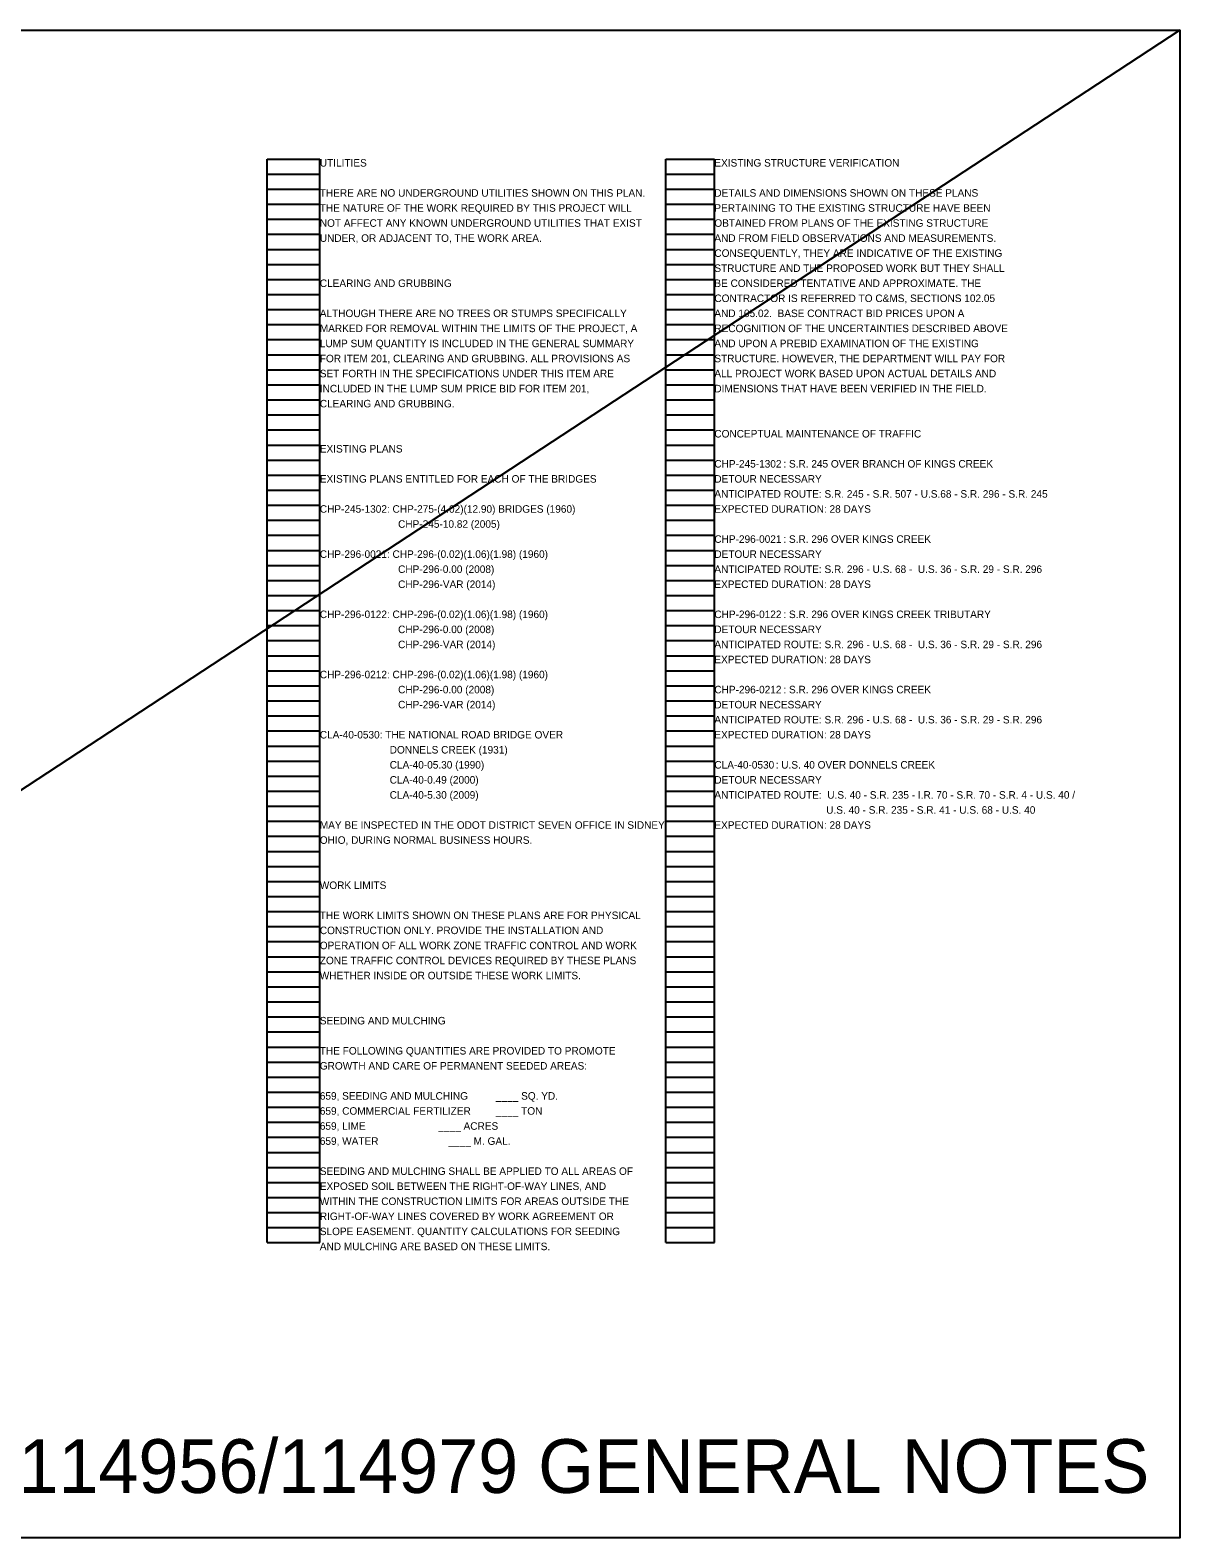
# Model space of a CAD drawing. Extents: x -49 to 78, y -12 to 34.
# Drawn here: x 56.89 to 78.28, y -4.7 to 23.35 of the extents above; entities that cross this region are included whole.
import ezdxf

# ---------------------------------------------------------------- set-up
doc = ezdxf.new("R2010")
doc.units = 0
for name, color, linetype in [('SC_Scratch1', 7, 'Continuous'), ('SH_Data', 7, 'Continuous'), ('SH_Text', 7, 'Continuous')]:
    doc.layers.add(name, color=color, linetype=linetype)

msp = doc.modelspace()

# ---------------------------------------------------------------- linework, layer by layer
at = {"layer": 'SC_Scratch1'}
msp.add_line((78.278, 23.346), (35.501, -4.704), dxfattribs=at)
msp.add_lwpolyline([(35.501, 23.346), (78.278, 23.346), (78.278, -4.704), (35.501, -4.704)], close=True, dxfattribs=at)
at = {"layer": 'SH_Data'}
for p, q in [((61.298, 0.788), (61.298, 20.948)), ((61.298, 20.948), (62.278, 20.948)), ((62.278, 0.788), (62.278, 20.948)), ((68.718, 0.788), (68.718, 20.948)), ((68.718, 20.948), (69.618, 20.948)), ((69.618, 0.788), (69.618, 20.948)), ((61.298, 20.668), (62.278, 20.668)), ((68.718, 20.668), (69.618, 20.668)), ((61.298, 20.388), (62.278, 20.388)), ((68.718, 20.388), (69.618, 20.388)), ((61.298, 20.108), (62.278, 20.108)), ((68.718, 20.108), (69.618, 20.108)), ((61.298, 19.828), (62.278, 19.828)), ((68.718, 19.828), (69.618, 19.828)), ((61.298, 19.548), (62.278, 19.548)), ((68.718, 19.548), (69.618, 19.548)), ((61.298, 19.268), (62.278, 19.268)), ((68.718, 19.268), (69.618, 19.268)), ((61.298, 18.988), (62.278, 18.988)), ((68.718, 18.988), (69.618, 18.988)), ((61.298, 18.708), (62.278, 18.708)), ((68.718, 18.708), (69.618, 18.708)), ((61.298, 18.428), (62.278, 18.428)), ((68.718, 18.428), (69.618, 18.428)), ((61.298, 18.148), (62.278, 18.148)), ((68.718, 18.148), (69.618, 18.148)), ((61.298, 17.868), (62.278, 17.868)), ((68.718, 17.868), (69.618, 17.868)), ((61.298, 17.588), (62.278, 17.588)), ((68.718, 17.588), (69.618, 17.588)), ((61.298, 17.308), (62.278, 17.308)), ((68.718, 17.308), (69.618, 17.308)), ((61.298, 17.028), (62.278, 17.028)), ((68.718, 17.028), (69.618, 17.028)), ((61.298, 16.748), (62.278, 16.748)), ((68.718, 16.748), (69.618, 16.748)), ((61.298, 16.468), (62.278, 16.468)), ((68.718, 16.468), (69.618, 16.468)), ((61.298, 16.188), (62.278, 16.188)), ((68.718, 16.188), (69.618, 16.188)), ((61.298, 15.908), (62.278, 15.908)), ((68.718, 15.908), (69.618, 15.908)), ((61.298, 15.628), (62.278, 15.628)), ((68.718, 15.628), (69.618, 15.628)), ((61.298, 15.348), (62.278, 15.348)), ((68.718, 15.348), (69.618, 15.348)), ((61.298, 15.068), (62.278, 15.068)), ((68.718, 15.068), (69.618, 15.068)), ((61.298, 14.788), (62.278, 14.788)), ((68.718, 14.788), (69.618, 14.788)), ((61.298, 14.508), (62.278, 14.508)), ((68.718, 14.508), (69.618, 14.508)), ((61.298, 14.228), (62.278, 14.228)), ((68.718, 14.228), (69.618, 14.228)), ((61.298, 13.948), (62.278, 13.948)), ((68.718, 13.948), (69.618, 13.948)), ((61.298, 13.668), (62.278, 13.668)), ((68.718, 13.668), (69.618, 13.668)), ((61.298, 13.388), (62.278, 13.388)), ((68.718, 13.388), (69.618, 13.388)), ((61.298, 13.108), (62.278, 13.108)), ((68.718, 13.108), (69.618, 13.108)), ((61.298, 12.828), (62.278, 12.828)), ((68.718, 12.828), (69.618, 12.828)), ((61.298, 12.548), (62.278, 12.548)), ((68.718, 12.548), (69.618, 12.548)), ((61.298, 12.268), (62.278, 12.268)), ((68.718, 12.268), (69.618, 12.268)), ((61.298, 11.988), (62.278, 11.988)), ((68.718, 11.988), (69.618, 11.988)), ((61.298, 11.708), (62.278, 11.708)), ((68.718, 11.708), (69.618, 11.708)), ((61.298, 11.428), (62.278, 11.428)), ((68.718, 11.428), (69.618, 11.428)), ((61.298, 11.148), (62.278, 11.148)), ((68.718, 11.148), (69.618, 11.148)), ((61.298, 10.868), (62.278, 10.868)), ((68.718, 10.868), (69.618, 10.868)), ((61.298, 10.588), (62.278, 10.588)), ((68.718, 10.588), (69.618, 10.588)), ((61.298, 10.308), (62.278, 10.308)), ((68.718, 10.308), (69.618, 10.308)), ((61.298, 10.028), (62.278, 10.028)), ((68.718, 10.028), (69.618, 10.028)), ((61.298, 9.748), (62.278, 9.748)), ((68.718, 9.748), (69.618, 9.748)), ((61.298, 9.468), (62.278, 9.468)), ((68.718, 9.468), (69.618, 9.468)), ((61.298, 9.188), (62.278, 9.188)), ((68.718, 9.188), (69.618, 9.188)), ((61.298, 8.908), (62.278, 8.908)), ((68.718, 8.908), (69.618, 8.908)), ((61.298, 8.628), (62.278, 8.628)), ((68.718, 8.628), (69.618, 8.628)), ((61.298, 8.348), (62.278, 8.348)), ((68.718, 8.348), (69.618, 8.348)), ((61.298, 8.068), (62.278, 8.068)), ((68.718, 8.068), (69.618, 8.068)), ((61.298, 7.788), (62.278, 7.788)), ((68.718, 7.788), (69.618, 7.788)), ((61.298, 7.508), (62.278, 7.508)), ((68.718, 7.508), (69.618, 7.508)), ((61.298, 7.228), (62.278, 7.228)), ((68.718, 7.228), (69.618, 7.228)), ((61.298, 6.948), (62.278, 6.948)), ((68.718, 6.948), (69.618, 6.948)), ((61.298, 6.668), (62.278, 6.668)), ((68.718, 6.668), (69.618, 6.668)), ((61.298, 6.388), (62.278, 6.388)), ((68.718, 6.388), (69.618, 6.388)), ((61.298, 6.108), (62.278, 6.108)), ((68.718, 6.108), (69.618, 6.108)), ((61.298, 5.828), (62.278, 5.828)), ((68.718, 5.828), (69.618, 5.828)), ((61.298, 5.548), (62.278, 5.548)), ((68.718, 5.548), (69.618, 5.548)), ((61.298, 5.268), (62.278, 5.268)), ((68.718, 5.268), (69.618, 5.268)), ((61.298, 4.988), (62.278, 4.988)), ((68.718, 4.988), (69.618, 4.988)), ((61.298, 4.708), (62.278, 4.708)), ((68.718, 4.708), (69.618, 4.708)), ((61.298, 4.428), (62.278, 4.428)), ((68.718, 4.428), (69.618, 4.428)), ((61.298, 4.148), (62.278, 4.148)), ((68.718, 4.148), (69.618, 4.148)), ((61.298, 3.868), (62.278, 3.868)), ((68.718, 3.868), (69.618, 3.868)), ((61.298, 3.588), (62.278, 3.588)), ((68.718, 3.588), (69.618, 3.588)), ((61.298, 3.308), (62.278, 3.308)), ((68.718, 3.308), (69.618, 3.308)), ((61.298, 3.028), (62.278, 3.028)), ((68.718, 3.028), (69.618, 3.028)), ((61.298, 2.748), (62.278, 2.748)), ((68.718, 2.748), (69.618, 2.748)), ((61.298, 2.468), (62.278, 2.468)), ((68.718, 2.468), (69.618, 2.468)), ((61.298, 2.188), (62.278, 2.188)), ((68.718, 2.188), (69.618, 2.188)), ((61.298, 1.908), (62.278, 1.908)), ((68.718, 1.908), (69.618, 1.908)), ((61.298, 1.628), (62.278, 1.628)), ((68.718, 1.628), (69.618, 1.628)), ((61.298, 1.348), (62.278, 1.348)), ((68.718, 1.348), (69.618, 1.348)), ((61.298, 1.068), (62.278, 1.068)), ((68.718, 1.068), (69.618, 1.068)), ((61.298, 0.788), (62.278, 0.788)), ((68.718, 0.788), (69.618, 0.788))]:
    msp.add_line(p, q, dxfattribs=at)

# ---------------------------------------------------------------- texts
at = {"layer": 'SC_Scratch1'}
msp.add_text('REF: 114956/114979 GENERAL NOTES', height=1, dxfattribs=at).set_placement((53.255, -3.869))
at = {"layer": 'SH_Text'}
for s, p in [('UTILITIES', (62.278, 20.808)), ('EXISTING STRUCTURE VERIFICATION', (69.618, 20.808)), ('THERE ARE NO UNDERGROUND UTILITIES SHOWN ON THIS PLAN. ', (62.278, 20.248)), ('DETAILS AND DIMENSIONS SHOWN ON THESE PLANS ', (69.618, 20.248)), ('THE NATURE OF THE WORK REQUIRED BY THIS PROJECT WILL ', (62.278, 19.968)), ('PERTAINING TO THE EXISTING STRUCTURE HAVE BEEN ', (69.618, 19.968)), ('NOT AFFECT ANY KNOWN UNDERGROUND UTILITIES THAT EXIST ', (62.278, 19.688)), ('OBTAINED FROM PLANS OF THE EXISTING STRUCTURE ', (69.618, 19.688)), ('UNDER, OR ADJACENT TO, THE WORK AREA.', (62.278, 19.408)), ('AND FROM FIELD OBSERVATIONS AND MEASUREMENTS. ', (69.618, 19.408)), ('CONSEQUENTLY, THEY ARE INDICATIVE OF THE EXISTING ', (69.618, 19.128)), ('STRUCTURE AND THE PROPOSED WORK BUT THEY SHALL ', (69.618, 18.848)), ('CLEARING AND GRUBBING', (62.278, 18.568)), ('BE CONSIDERED TENTATIVE AND APPROXIMATE. THE ', (69.618, 18.568)), ('CONTRACTOR IS REFERRED TO C&MS, SECTIONS 102.05 ', (69.618, 18.288)), ('ALTHOUGH THERE ARE NO TREES OR STUMPS SPECIFICALLY ', (62.278, 18.008)), ('AND 105.02.  BASE CONTRACT BID PRICES UPON A ', (69.618, 18.008)), ('MARKED FOR REMOVAL WITHIN THE LIMITS OF THE PROJECT, A ', (62.278, 17.728)), ('RECOGNITION OF THE UNCERTAINTIES DESCRIBED ABOVE ', (69.618, 17.728)), ('LUMP SUM QUANTITY IS INCLUDED IN THE GENERAL SUMMARY ', (62.278, 17.448)), ('AND UPON A PREBID EXAMINATION OF THE EXISTING ', (69.618, 17.448)), ('FOR ITEM 201, CLEARING AND GRUBBING. ALL PROVISIONS AS ', (62.278, 17.168)), ('STRUCTURE. HOWEVER, THE DEPARTMENT WILL PAY FOR ', (69.618, 17.168)), ('SET FORTH IN THE SPECIFICATIONS UNDER THIS ITEM ARE ', (62.278, 16.888)), ('ALL PROJECT WORK BASED UPON ACTUAL DETAILS AND ', (69.618, 16.888)), ('INCLUDED IN THE LUMP SUM PRICE BID FOR ITEM 201, ', (62.278, 16.608)), ('DIMENSIONS THAT HAVE BEEN VERIFIED IN THE FIELD.', (69.618, 16.608)), ('CLEARING AND GRUBBING.', (62.278, 16.328)), ('CONCEPTUAL MAINTENANCE OF TRAFFIC', (69.618, 15.768)), ('EXISTING PLANS', (62.278, 15.488)), ('CHP-245-1302', (69.618, 15.208)), (': S.R. 245 OVER BRANCH OF KINGS CREEK', (70.902, 15.208)), ('EXISTING PLANS ENTITLED FOR EACH OF THE BRIDGES', (62.278, 14.928)), ('DETOUR NECESSARY', (69.618, 14.928)), ('ANTICIPATED ROUTE: S.R. 245 - S.R. 507 - U.S.68 - S.R. 296 - S.R. 245', (69.618, 14.648)), ('CHP-245-1302: CHP-275-(4.02)(12.90) BRIDGES (1960)', (62.278, 14.368)), ('EXPECTED DURATION: 28 DAYS', (69.618, 14.368)), ('                            CHP-245-10.82 (2005)', (62.278, 14.088)), ('CHP-296-0021', (69.618, 13.808)), (': S.R. 296 OVER KINGS CREEK', (70.902, 13.808)), ('CHP-296-0021: CHP-296-(0.02)(1.06)(1.98) (1960)', (62.278, 13.528)), ('DETOUR NECESSARY', (69.618, 13.528)), ('                            CHP-296-0.00 (2008)', (62.278, 13.248)), ('ANTICIPATED ROUTE: S.R. 296 - U.S. 68 -  U.S. 36 - S.R. 29 - S.R. 296', (69.618, 13.248)), ('                            CHP-296-VAR (2014)', (62.278, 12.968)), ('EXPECTED DURATION: 28 DAYS', (69.618, 12.968)), ('CHP-296-0122: CHP-296-(0.02)(1.06)(1.98) (1960)', (62.278, 12.408)), ('CHP-296-0122', (69.618, 12.408)), (': S.R. 296 OVER KINGS CREEK TRIBUTARY', (70.902, 12.408)), ('                            CHP-296-0.00 (2008)', (62.278, 12.128)), ('DETOUR NECESSARY', (69.618, 12.128)), ('                            CHP-296-VAR (2014)', (62.278, 11.848)), ('ANTICIPATED ROUTE: S.R. 296 - U.S. 68 -  U.S. 36 - S.R. 29 - S.R. 296', (69.618, 11.848)), ('EXPECTED DURATION: 28 DAYS', (69.618, 11.568)), ('CHP-296-0212: CHP-296-(0.02)(1.06)(1.98) (1960)', (62.278, 11.288)), ('                            CHP-296-0.00 (2008)', (62.278, 11.008)), ('CHP-296-0212', (69.618, 11.008)), (': S.R. 296 OVER KINGS CREEK', (70.902, 11.008)), ('                            CHP-296-VAR (2014)', (62.278, 10.728)), ('DETOUR NECESSARY', (69.618, 10.728)), ('ANTICIPATED ROUTE: S.R. 296 - U.S. 68 -  U.S. 36 - S.R. 29 - S.R. 296', (69.618, 10.448)), ('CLA-40-0530: THE NATIONAL ROAD BRIDGE OVER ', (62.278, 10.168)), ('EXPECTED DURATION: 28 DAYS', (69.618, 10.168)), ('                         DONNELS CREEK (1931)', (62.278, 9.888)), ('                         CLA-40-05.30 (1990)', (62.278, 9.608)), ('CLA-40-0530', (69.618, 9.608)), (': U.S. 40 OVER DONNELS CREEK', (70.759, 9.608)), ('                         CLA-40-0.49 (2000)', (62.278, 9.328)), ('DETOUR NECESSARY', (69.618, 9.328)), ('                         CLA-40-5.30 (2009)', (62.278, 9.048)), ('ANTICIPATED ROUTE:  U.S. 40 - S.R. 235 - I.R. 70 - S.R. 70 - S.R. 4 - U.S. 40 /       ', (69.618, 9.048)), ('                                        U.S. 40 - S.R. 235 - S.R. 41 - U.S. 68 - U.S. 40 ', (69.618, 8.768)), ('MAY BE INSPECTED IN THE ODOT DISTRICT SEVEN OFFICE IN SIDNEY, ', (62.278, 8.488)), ('EXPECTED DURATION: 28 DAYS', (69.618, 8.488)), ('OHIO, DURING NORMAL BUSINESS HOURS.', (62.278, 8.208)), ('WORK LIMITS', (62.278, 7.368)), ('THE WORK LIMITS SHOWN ON THESE PLANS ARE FOR PHYSICAL ', (62.278, 6.808)), ('CONSTRUCTION ONLY. PROVIDE THE INSTALLATION AND ', (62.278, 6.528)), ('OPERATION OF ALL WORK ZONE TRAFFIC CONTROL AND WORK ', (62.278, 6.248)), ('ZONE TRAFFIC CONTROL DEVICES REQUIRED BY THESE PLANS ', (62.278, 5.968)), ('WHETHER INSIDE OR OUTSIDE THESE WORK LIMITS.', (62.278, 5.688)), ('SEEDING AND MULCHING', (62.278, 4.848)), ('THE FOLLOWING QUANTITIES ARE PROVIDED TO PROMOTE ', (62.278, 4.288)), ('GROWTH AND CARE OF PERMANENT SEEDED AREAS:', (62.278, 4.008)), ('659, SEEDING AND MULCHING          ____ SQ. YD.', (62.278, 3.448)), ('659, COMMERCIAL FERTILIZER         ____ TON', (62.278, 3.168)), ('659, LIME                          ____ ACRES', (62.278, 2.888)), ('659, WATER                         ____ M. GAL.', (62.278, 2.608)), ('SEEDING AND MULCHING SHALL BE APPLIED TO ALL AREAS OF ', (62.278, 2.048)), ('EXPOSED SOIL BETWEEN THE RIGHT-OF-WAY LINES, AND ', (62.278, 1.768)), ('WITHIN THE CONSTRUCTION LIMITS FOR AREAS OUTSIDE THE ', (62.278, 1.488)), ('RIGHT-OF-WAY LINES COVERED BY WORK AGREEMENT OR ', (62.278, 1.208)), ('SLOPE EASEMENT. QUANTITY CALCULATIONS FOR SEEDING ', (62.278, 0.928)), ('AND MULCHING ARE BASED ON THESE LIMITS.', (62.278, 0.648))]:
    msp.add_text(s, height=0.14, dxfattribs=at).set_placement(p)

doc.saveas('drawing.dxf')
